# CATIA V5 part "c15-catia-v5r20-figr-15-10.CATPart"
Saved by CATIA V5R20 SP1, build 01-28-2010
Part number: Part1
Bounding box of the stored display mesh (mm): x -50 to 50, y -32.5 to 33.5, z -52 to 1
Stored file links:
  D:\v5_r20\psrt_files_downloaded\c15\c15-catia-v5r20-figr-15-10.CATPart
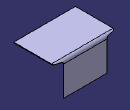
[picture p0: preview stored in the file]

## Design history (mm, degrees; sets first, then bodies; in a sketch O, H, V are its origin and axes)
SheetMetalParameters1: Thickness 1, BendRadius 4, KFactor 0.475772 {= log(min(100,max(20*SheetMetalParameters1.BendRadius,SheetMetalParameters1.Thickness)/SheetMetalParameters1.Thickness))/log(100)/2}, ReliefRadialLength 4, ReliefAxialLength 4, MinimumBendRadius 0
Body1 (main body)
  Sketch1 on xy-plane, origin (0, 0, 0), H (1, 0, 0), V (0, 1, 0)
    line L1 (-50, 32.5) -> (50, 32.5)
    line L2 (50, 32.5) -> (50, -32.5)
    line L3 (50, -32.5) -> (-50, -32.5)
    line L4 (-50, -32.5) -> (-50, 32.5)
    length L1 = 100
    length L2 = 65
    horizontal: L1 H, L3 H
    vertical: L2 V, L4 V
    symmetry: L4 L2 V, L1 L3 H
  Wall1: Thickness 1, Profile Sketch1
  d_NewWallOnEdge1: NewWallOnEdge_Edge edge [face of Wall1 | face of Wall1], NewWallOnEdge_Length 53, NewWallOnEdge_HeightLimitOffset 0, NewWallOnEdge_WidthOffset1 -15, NewWallOnEdge_WidthOffset2 -15, NewWallOnEdge_Angle 90, NewWallOnEdge_BendRadiusValue 4 {= SheetMetalParameters1.BendRadius}, NewWallOnEdge_BendTable SheetMetalParameters1, KFacteur 0.475772 {= log(min(100,max(20*d_NewWallOnEdge1.Radius,SheetMetalParameters1.Thickness)/SheetMetalParameters1.Thickness))/log(100)/2}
